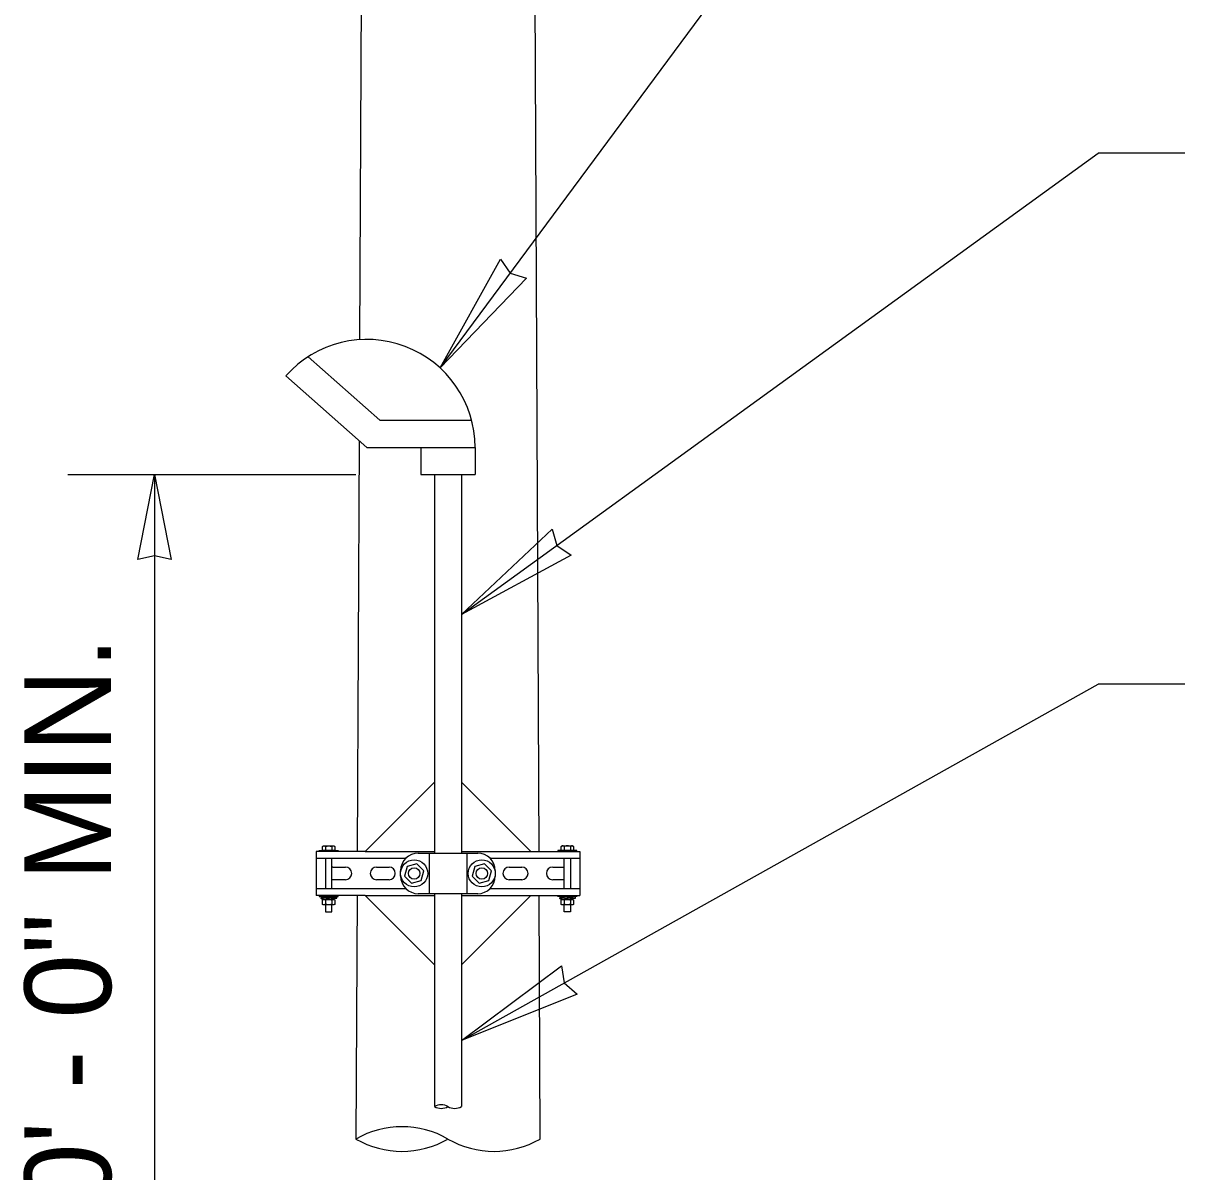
# Model space of a CAD drawing. Extents: x 99862 to 103151, y 100000 to 105076.
# Drawn here: x 101393.5 to 101608.2, y 101503.8 to 101716.2 of the extents above; entities that cross this region are included whole.
import ezdxf

# ---------------------------------------------------------------- set-up
doc = ezdxf.new("R2010")
doc.units = 0
for name, color, linetype in [('Level 1', 7, 'Continuous'), ('Level 13', 7, 'Continuous'), ('Level 15', 7, 'Continuous'), ('Level 20', 7, 'Continuous'), ('Level 4', 7, 'Continuous'), ('Level 5', 7, 'Continuous'), ('Level 6', 7, 'Continuous'), ('Level 8', 7, 'Continuous')]:
    doc.layers.add(name, color=color, linetype=linetype)

msp = doc.modelspace()

# ---------------------------------------------------------------- linework, layer by layer
at = {"layer": 'Level 1'}
for p, q in [((101456.88, 101927.16), (101455.66, 101657.68)), ((101487.13, 101927.16), (101488.77, 101563.05)), ((101459.4, 101642.83), (101446.18, 101654.54)), ((101457, 101637.74), (101442.05, 101650.99)), ((101459.4, 101642.83), (101476.34, 101642.82)), ((101455.58, 101639), (101455.23, 101563.05)), ((101457, 101637.74), (101477, 101637.74)), ((101467, 101637.74), (101467, 101632.74)), ((101477, 101637.74), (101477, 101632.74)), ((101467, 101632.74), (101477, 101632.74)), ((101469.5, 101632.74), (101469.5, 101562.74)), ((101474.5, 101632.74), (101474.5, 101562.74)), ((101447.63, 101563.05), (101447.63, 101554.92)), ((101456.69, 101563.05), (101447.63, 101563.05)), ((101447.63, 101561.8), (101464.22, 101561.8)), ((101456.69, 101563.05), (101469.5, 101563.05)), ((101466.5, 101562.74), (101477.5, 101562.74)), ((101468.5, 101562.74), (101468.5, 101555.24)), ((101474.5, 101563.05), (101487.32, 101563.05)), ((101475.5, 101562.74), (101475.5, 101555.24)), ((101479.79, 101561.8), (101496.38, 101561.8)), ((101487.32, 101563.05), (101496.38, 101563.05)), ((101496.38, 101563.05), (101496.38, 101554.92)), ((101450.75, 101560.15), (101453.07, 101560.15)), ((101458.79, 101560.15), (101461.11, 101560.15)), ((101463.25, 101558.49), (101463.25, 101559.49)), ((101480.75, 101559.49), (101480.75, 101558.49)), ((101483.33, 101560.15), (101485.65, 101560.15)), ((101491.37, 101560.15), (101493.48, 101560.15)), ((101453.07, 101557.82), (101450.75, 101557.82)), ((101461.11, 101557.82), (101458.79, 101557.82)), ((101485.65, 101557.82), (101483.33, 101557.82)), ((101493.48, 101557.82), (101491.37, 101557.82)), ((101447.63, 101556.17), (101464.22, 101556.17)), ((101477.5, 101555.24), (101466.5, 101555.24)), ((101469.5, 101555.24), (101469.5, 101515.87)), ((101474.5, 101555.24), (101474.5, 101515.87)), ((101479.79, 101556.17), (101496.38, 101556.17)), ((101456.69, 101554.92), (101447.63, 101554.92)), ((101455.2, 101554.92), (101454.99, 101509.87)), ((101456.69, 101554.92), (101469.5, 101554.92)), ((101474.5, 101554.92), (101487.32, 101554.92)), ((101487.32, 101554.92), (101496.38, 101554.92)), ((101488.81, 101554.92), (101489.01, 101509.87))]:
    msp.add_line(p, q, dxfattribs=at)
for centre, radius, start, end in [((101457.02, 101637.74), 19.99, 359.9953, 138.4713), ((101466.5, 101559.49), 3.25, 90, 180), ((101477.5, 101559.49), 3.25, 0, 90), ((101450.75, 101558.99), 1.16, 90, 100.7661), ((101453.07, 101558.99), 1.16, 270, 90), ((101458.79, 101558.99), 1.16, 90, 270), ((101461.11, 101558.99), 1.16, 270, 90), ((101483.33, 101558.99), 1.16, 90, 270), ((101485.65, 101558.99), 1.16, 270, 90), ((101491.37, 101558.99), 1.16, 90, 270), ((101450.75, 101558.99), 1.16, 259.2339, 270), ((101466.5, 101558.49), 3.25, 180, 270), ((101477.5, 101558.49), 3.25, 270, 0), ((101470.75, 101513.7), 2.5, 60, 120), ((101470.75, 101518.03), 2.5, 240, 300), ((101473.25, 101518.03), 2.5, 240, 300), ((101463.5, 101495.14), 17.01, 60, 120), ((101463.5, 101524.6), 17.01, 240, 300), ((101480.51, 101524.6), 17.01, 240, 300)]:
    msp.add_arc(centre, radius, start, end, dxfattribs=at)
at = {"layer": 'Level 13'}
for points in [[(101456.69, 101563.05), (101469.5, 101575.86)], [(101474.5, 101575.86), (101487.32, 101563.05)], [(101469.5, 101542.11), (101456.69, 101554.92)], [(101487.32, 101554.92), (101474.5, 101542.11)]]:
    msp.add_lwpolyline(points, dxfattribs=at)
at = {"layer": 'Level 15'}
for p, q in [((101470.53, 101652.47), (101592.18, 101816.81)), ((101474.5, 101606.84), (101592.18, 101692.19)), ((101608.18, 101692.19), (101592.18, 101692.19)), ((101401.73, 101632.74), (101455, 101632.74)), ((101417.73, 101632.74), (101417.73, 101458.92)), ((101474.5, 101528.11), (101592.18, 101594.01)), ((101608.18, 101594.01), (101592.18, 101594.01))]:
    msp.add_line(p, q, dxfattribs=at)
for points in [[(101470.53, 101652.47), (101481.71, 101672.59), (101483.48, 101669.97), (101486.51, 101669.04)], [(101417.73, 101632.74), (101420.82, 101617.01), (101417.73, 101617.74), (101414.65, 101617.01)], [(101474.5, 101606.84), (101491.23, 101622.66), (101492.13, 101619.63), (101494.74, 101617.83)], [(101474.5, 101528.11), (101492.96, 101541.87), (101493.5, 101538.75), (101495.88, 101536.66)]]:
    msp.add_lwpolyline(points, close=True, dxfattribs=at)
at = {"layer": 'Level 4'}
for p, q in [((101448.79, 101563.99), (101449.02, 101564.11)), ((101448.79, 101563.24), (101448.79, 101563.99)), ((101449.02, 101564.11), (101450.88, 101564.11)), ((101449.37, 101563.99), (101449.37, 101563.24)), ((101450.53, 101563.99), (101450.53, 101563.24)), ((101450.88, 101564.11), (101451.11, 101563.99)), ((101451.11, 101563.99), (101451.11, 101563.24)), ((101492.9, 101563.99), (101493.13, 101564.11)), ((101492.9, 101563.24), (101492.9, 101563.99)), ((101493.13, 101564.11), (101494.99, 101564.11)), ((101493.48, 101563.99), (101493.48, 101563.24)), ((101494.64, 101563.99), (101494.64, 101563.24)), ((101494.99, 101564.11), (101495.22, 101563.99)), ((101495.22, 101563.99), (101495.22, 101563.24)), ((101449.37, 101563.24), (101448.79, 101563.24)), ((101450.53, 101563.24), (101449.37, 101563.24)), ((101449.37, 101561.8), (101449.37, 101556.17)), ((101451.11, 101563.24), (101450.53, 101563.24)), ((101450.53, 101556.17), (101450.53, 101561.8)), ((101493.48, 101563.24), (101492.9, 101563.24)), ((101494.64, 101563.24), (101493.48, 101563.24)), ((101493.48, 101556.17), (101493.48, 101561.8)), ((101495.22, 101563.24), (101494.64, 101563.24)), ((101494.64, 101561.8), (101494.64, 101556.17)), ((101449.37, 101554.5), (101449.37, 101554.75)), ((101449.37, 101553.15), (101449.37, 101551.9)), ((101450.53, 101554.22), (101450.53, 101554.47)), ((101450.53, 101551.9), (101450.53, 101553.15)), ((101493.48, 101554.5), (101493.48, 101554.75)), ((101493.48, 101551.9), (101493.48, 101553.15)), ((101494.64, 101554.47), (101494.64, 101554.22)), ((101494.64, 101553.15), (101494.64, 101551.9)), ((101449.37, 101551.9), (101450.53, 101551.9)), ((101494.64, 101551.9), (101493.48, 101551.9))]:
    msp.add_line(p, q, dxfattribs=at)
for points, degree in [([(101448.79, 101563.99), (101448.84, 101564.02), (101448.89, 101564.04), (101448.98, 101564.07), (101449.03, 101564.07), (101449.1, 101564.07), (101449.13, 101564.07), (101449.18, 101564.06), (101449.25, 101564.05), (101449.32, 101564.02), (101449.37, 101563.99)], 3), ([(101448.79, 101563.99), (101448.79, 101563.99), (101448.79, 101563.99), (101448.79, 101563.99)], 2), ([(101449.37, 101563.99), (101449.46, 101564.02), (101449.61, 101564.05), (101449.75, 101564.06), (101449.85, 101564.07), (101449.9, 101564.07), (101450.05, 101564.07), (101450.15, 101564.07), (101450.34, 101564.04), (101450.44, 101564.02), (101450.53, 101563.99)], 3), ([(101450.53, 101563.99), (101450.58, 101564.02), (101450.63, 101564.04), (101450.72, 101564.07), (101450.77, 101564.07), (101450.85, 101564.07), (101450.87, 101564.07), (101450.92, 101564.06), (101450.99, 101564.05), (101451.06, 101564.02), (101451.11, 101563.99)], 3), ([(101451.11, 101563.99), (101451.11, 101563.99), (101451.11, 101563.99), (101451.11, 101563.99)], 2), ([(101493.48, 101563.99), (101493.43, 101564.02), (101493.38, 101564.04), (101493.29, 101564.07), (101493.24, 101564.07), (101493.16, 101564.07), (101493.14, 101564.07), (101493.09, 101564.06), (101493.02, 101564.05), (101492.95, 101564.02), (101492.9, 101563.99)], 3), ([(101492.9, 101563.99), (101492.9, 101563.99), (101492.9, 101563.99), (101492.9, 101563.99)], 2), ([(101494.64, 101563.99), (101494.54, 101564.02), (101494.4, 101564.05), (101494.26, 101564.06), (101494.16, 101564.07), (101494.11, 101564.07), (101493.96, 101564.07), (101493.86, 101564.07), (101493.67, 101564.04), (101493.57, 101564.02), (101493.48, 101563.99)], 3), ([(101495.22, 101563.99), (101495.17, 101564.02), (101495.12, 101564.04), (101495.03, 101564.07), (101494.98, 101564.07), (101494.9, 101564.07), (101494.88, 101564.07), (101494.83, 101564.06), (101494.76, 101564.05), (101494.69, 101564.02), (101494.64, 101563.99)], 3), ([(101495.22, 101563.99), (101495.22, 101563.99), (101495.22, 101563.99), (101495.22, 101563.99)], 2)]:
    msp.add_open_spline(points, degree=degree, dxfattribs=at)
at = {"layer": 'Level 5'}
for p, q in [((101448.21, 101563.05), (101448.21, 101563.22)), ((101448.21, 101563.22), (101451.69, 101563.22)), ((101451.69, 101563.22), (101451.69, 101563.05)), ((101495.8, 101563.22), (101492.32, 101563.22)), ((101492.32, 101563.22), (101492.32, 101563.05)), ((101495.8, 101563.05), (101495.8, 101563.22)), ((101448.21, 101554.92), (101448.21, 101554.75)), ((101448.21, 101554.75), (101451.69, 101554.75)), ((101451.69, 101554.75), (101451.69, 101554.92)), ((101492.32, 101554.75), (101492.32, 101554.92)), ((101495.8, 101554.75), (101492.32, 101554.75)), ((101495.8, 101554.92), (101495.8, 101554.75))]:
    msp.add_line(p, q, dxfattribs=at)
at = {"layer": 'Level 6'}
for p, q in [((101448.57, 101554.32), (101448.57, 101554.34)), ((101448.6, 101554.59), (101448.58, 101554.59)), ((101449.05, 101554.61), (101448.6, 101554.59)), ((101450.02, 101554.48), (101450.01, 101554.22)), ((101450.05, 101554.48), (101450.05, 101554.75)), ((101450.97, 101554.41), (101451.46, 101554.41)), ((101492.68, 101554.32), (101492.68, 101554.34)), ((101492.71, 101554.59), (101492.69, 101554.59)), ((101493.16, 101554.6), (101492.71, 101554.59)), ((101494.12, 101554.48), (101494.12, 101554.22)), ((101494.15, 101554.48), (101494.16, 101554.75)), ((101495.07, 101554.41), (101495.57, 101554.4))]:
    msp.add_line(p, q, dxfattribs=at)
for centre, major_axis, ratio, start_param, end_param in [((101450.02, 101554.62), (0.48, 26.26), 0.054836, 1.572979, 1.582484), ((101450.01, 101554.3), (1.44, -0.03), 0.055504, 3.154008, 4.712408), ((101450.02, 101554.56), (1.44, -0.03), 0.055504, 3.143736, 4.712408), ((101450, 101554.64), (-0.953, -0.036), 0.000669, 5.438318, 6.283167), ((101450.02, 101554.7), (1.44, -0.02), 0.03659, 0.009819, 1.552783), ((101450.02, 101554.43), (1.44, -0.02), 0.03659, 0.003052, 1.552783), ((101450.01, 101554.38), (-0.953, -0.036), 0.000669, 3.172017, 4.137477), ((101450.02, 101554.31), (0.67, 39.36), 0.03659, 4.715441, 4.722208), ((101494.13, 101554.62), (0.48, 26.26), 0.054836, 1.572979, 1.582484), ((101494.12, 101554.3), (1.44, -0.03), 0.055504, 3.154008, 4.712408), ((101494.13, 101554.56), (1.44, -0.03), 0.055504, 3.143736, 4.712408), ((101494.11, 101554.64), (-0.953, -0.036), 0.000669, 5.438318, 6.283167), ((101494.13, 101554.43), (1.44, -0.02), 0.03659, 0.003052, 1.552783), ((101494.13, 101554.7), (1.44, -0.02), 0.03659, 0.009819, 1.552783), ((101494.12, 101554.37), (-0.953, -0.036), 0.000669, 3.172017, 4.137477), ((101494.12, 101554.31), (0.67, 39.36), 0.03659, 4.715441, 4.722208)]:
    msp.add_ellipse(centre, major_axis=major_axis, ratio=ratio, start_param=start_param, end_param=end_param, dxfattribs=at)
at = {"layer": 'Level 8'}
for p, q in [((101448.79, 101554.09), (101449.02, 101554.22)), ((101448.79, 101553.27), (101448.79, 101554.09)), ((101449.02, 101553.15), (101448.79, 101553.27)), ((101449.02, 101554.22), (101450.88, 101554.22)), ((101450.88, 101553.15), (101449.02, 101553.15)), ((101449.37, 101554.09), (101449.37, 101553.27)), ((101450.53, 101554.09), (101450.53, 101553.27)), ((101450.88, 101554.22), (101451.11, 101554.09)), ((101451.11, 101553.27), (101450.88, 101553.15)), ((101451.11, 101554.09), (101451.11, 101553.27)), ((101492.9, 101554.09), (101493.13, 101554.22)), ((101492.9, 101553.27), (101492.9, 101554.09)), ((101493.13, 101553.15), (101492.9, 101553.27)), ((101493.13, 101554.22), (101494.99, 101554.22)), ((101494.99, 101553.15), (101493.13, 101553.15)), ((101493.48, 101554.09), (101493.48, 101553.27)), ((101494.64, 101554.09), (101494.64, 101553.27)), ((101494.99, 101554.22), (101495.22, 101554.09)), ((101495.22, 101553.27), (101494.99, 101553.15)), ((101495.22, 101554.09), (101495.22, 101553.27))]:
    msp.add_line(p, q, dxfattribs=at)
for points in [[(101464.45, 101560.29), (101463.97, 101558.51), (101465.28, 101557.2), (101467.06, 101557.68), (101467.54, 101559.46), (101466.23, 101560.77)], [(101476.95, 101560.29), (101476.47, 101558.51), (101477.78, 101557.2), (101479.56, 101557.68), (101480.04, 101559.46), (101478.73, 101560.77)]]:
    msp.add_lwpolyline(points, close=True, dxfattribs=at)
for centre, radius in [((101465.75, 101558.99), 2.5), ((101478.25, 101558.99), 2.5), ((101465.75, 101558.99), 1.06), ((101478.25, 101558.99), 1.06)]:
    msp.add_circle(centre, radius, dxfattribs=at)
for points, degree in [([(101448.79, 101554.09), (101448.84, 101554.12), (101448.89, 101554.14), (101448.98, 101554.17), (101449.03, 101554.18), (101449.1, 101554.18), (101449.13, 101554.17), (101449.18, 101554.17), (101449.25, 101554.15), (101449.32, 101554.12), (101449.37, 101554.09)], 3), ([(101448.79, 101554.09), (101448.79, 101554.09), (101448.79, 101554.09), (101448.79, 101554.09)], 2), ([(101448.79, 101553.27), (101448.79, 101553.27), (101448.79, 101553.27), (101448.79, 101553.27)], 2), ([(101449.37, 101553.27), (101449.32, 101553.25), (101449.25, 101553.21), (101449.18, 101553.2), (101449.13, 101553.19), (101449.1, 101553.19), (101449.03, 101553.19), (101448.98, 101553.2), (101448.89, 101553.22), (101448.84, 101553.25), (101448.79, 101553.27)], 3), ([(101449.37, 101554.09), (101449.46, 101554.12), (101449.61, 101554.15), (101449.75, 101554.17), (101449.85, 101554.17), (101449.9, 101554.18), (101450.05, 101554.18), (101450.15, 101554.17), (101450.34, 101554.14), (101450.44, 101554.12), (101450.53, 101554.09)], 3), ([(101450.53, 101553.27), (101450.44, 101553.25), (101450.34, 101553.22), (101450.15, 101553.2), (101450.05, 101553.19), (101449.9, 101553.19), (101449.85, 101553.19), (101449.75, 101553.2), (101449.61, 101553.21), (101449.46, 101553.25), (101449.37, 101553.27)], 3), ([(101450.53, 101554.09), (101450.58, 101554.12), (101450.63, 101554.14), (101450.72, 101554.17), (101450.77, 101554.18), (101450.85, 101554.18), (101450.87, 101554.17), (101450.92, 101554.17), (101450.99, 101554.15), (101451.06, 101554.12), (101451.11, 101554.09)], 3), ([(101451.11, 101553.27), (101451.06, 101553.25), (101450.99, 101553.21), (101450.92, 101553.2), (101450.87, 101553.19), (101450.85, 101553.19), (101450.77, 101553.19), (101450.72, 101553.2), (101450.63, 101553.22), (101450.58, 101553.25), (101450.53, 101553.27)], 3), ([(101451.11, 101554.09), (101451.11, 101554.09), (101451.11, 101554.09), (101451.11, 101554.09)], 2), ([(101451.11, 101553.27), (101451.11, 101553.27), (101451.11, 101553.27), (101451.11, 101553.27)], 2), ([(101492.9, 101554.09), (101492.95, 101554.12), (101493.02, 101554.15), (101493.09, 101554.17), (101493.14, 101554.17), (101493.16, 101554.17), (101493.24, 101554.17), (101493.29, 101554.17), (101493.38, 101554.14), (101493.43, 101554.12), (101493.48, 101554.09)], 3), ([(101492.9, 101554.09), (101492.9, 101554.09), (101492.9, 101554.09), (101492.9, 101554.09)], 2), ([(101492.9, 101553.27), (101492.9, 101553.27), (101492.9, 101553.27), (101492.9, 101553.27)], 2), ([(101493.48, 101553.27), (101493.43, 101553.24), (101493.38, 101553.22), (101493.29, 101553.19), (101493.24, 101553.19), (101493.16, 101553.19), (101493.14, 101553.19), (101493.09, 101553.2), (101493.02, 101553.21), (101492.95, 101553.24), (101492.9, 101553.27)], 3), ([(101493.48, 101554.09), (101493.57, 101554.12), (101493.67, 101554.14), (101493.86, 101554.17), (101493.96, 101554.17), (101494.11, 101554.17), (101494.16, 101554.17), (101494.26, 101554.17), (101494.4, 101554.15), (101494.54, 101554.12), (101494.64, 101554.09)], 3), ([(101494.64, 101553.27), (101494.54, 101553.24), (101494.4, 101553.21), (101494.26, 101553.2), (101494.16, 101553.19), (101494.11, 101553.19), (101493.96, 101553.19), (101493.86, 101553.19), (101493.67, 101553.22), (101493.57, 101553.24), (101493.48, 101553.27)], 3), ([(101494.64, 101554.09), (101494.69, 101554.12), (101494.76, 101554.15), (101494.83, 101554.17), (101494.88, 101554.17), (101494.9, 101554.17), (101494.98, 101554.17), (101495.03, 101554.17), (101495.12, 101554.14), (101495.17, 101554.12), (101495.22, 101554.09)], 3), ([(101495.22, 101553.27), (101495.17, 101553.24), (101495.12, 101553.22), (101495.03, 101553.19), (101494.98, 101553.19), (101494.9, 101553.19), (101494.88, 101553.19), (101494.83, 101553.2), (101494.76, 101553.21), (101494.69, 101553.24), (101494.64, 101553.27)], 3), ([(101495.22, 101554.09), (101495.22, 101554.09), (101495.22, 101554.09), (101495.22, 101554.09)], 2), ([(101495.22, 101553.27), (101495.22, 101553.27), (101495.22, 101553.27), (101495.22, 101553.27)], 2)]:
    msp.add_open_spline(points, degree=degree, dxfattribs=at)

# ---------------------------------------------------------------- texts
at = {"layer": 'Level 20'}
msp.add_text('10\' - 0" MIN.', height=16, rotation=90, dxfattribs=at).set_placement((101409.73, 101485.26))

doc.saveas('drawing.dxf')
